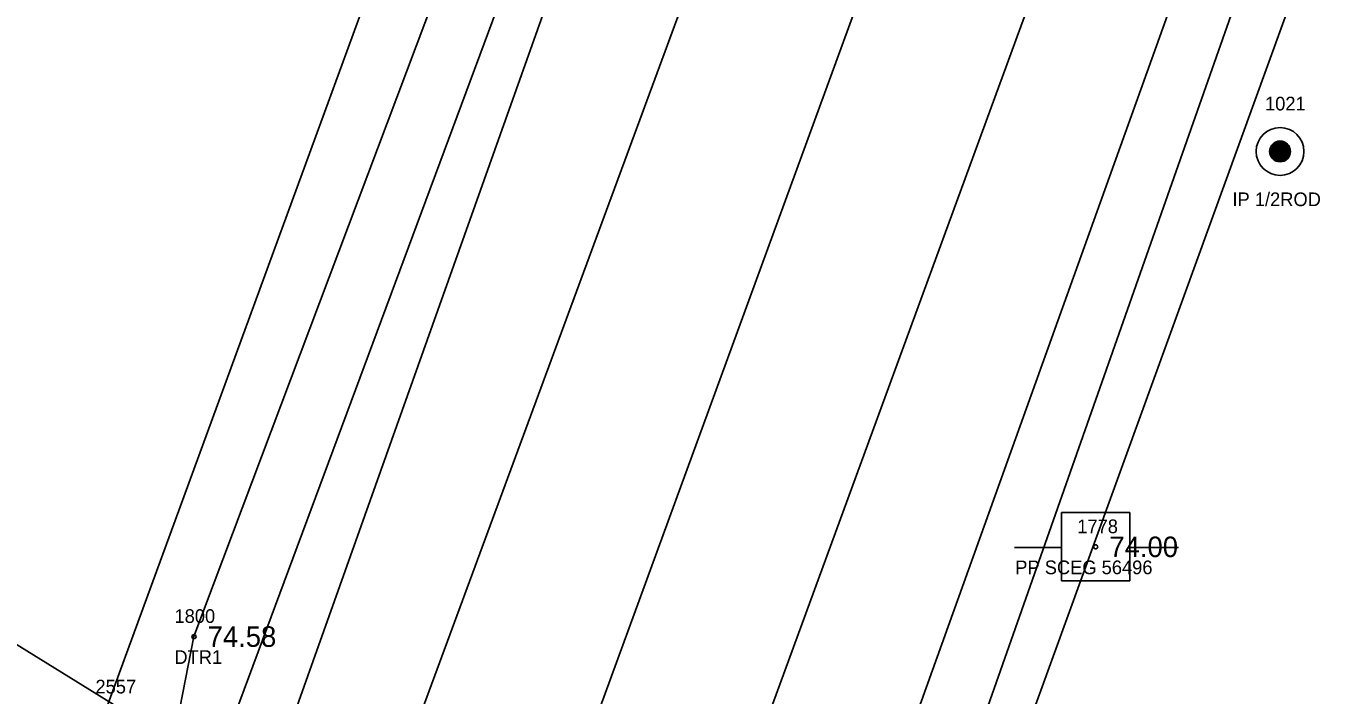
# Model space of a CAD drawing. Extents: x 2139392 to 2143384, y 505395 to 510520.
# Drawn here: x 2140931.1 to 2141025.8, y 509096.6 to 509145.6 of the extents above; entities that cross this region are included whole.
import ezdxf

# ---------------------------------------------------------------- set-up
doc = ezdxf.new("R2010")
doc.units = 0
for name, color, linetype in [('RD_EV_EX_Wetlands', 7, 'Continuous'), ('RD_EX_DV_Prop_txCode', 7, 'Continuous'), ('RD_EX_DV_PropPin', 7, 'Continuous'), ('RD_EX_H2O', 7, 'Continuous'), ('RD_EX_H2O_txCode', 7, 'Continuous'), ('RD_EX_Road', 7, 'Continuous'), ('RD_EX_TX_H2O_ELEV', 7, 'Continuous'), ('RD_EX_UT', 7, 'Continuous'), ('RD_EX_UT_txCode', 7, 'Continuous'), ('RD_EX_VEG', 7, 'Continuous'), ('RD_HC_Cl', 7, 'Continuous'), ('RD_HC_Survey_ELEV', 7, 'Continuous'), ('RD_SMD_Locator', 7, 'Continuous')]:
    doc.layers.add(name, color=color, linetype=linetype)

msp = doc.modelspace()

# ---------------------------------------------------------------- linework, layer by layer
at = {"layer": 'RD_EV_EX_Wetlands'}
for p, q in [((2141031.306, 509324.164), (2140691.527, 508408.628)), ((2141075.304, 509306.136), (2140751.402, 508384.33))]:
    msp.add_line(p, q, dxfattribs=at)
at = {"layer": 'RD_EX_DV_PropPin'}
for p, q in [((2141022.027, 509136.196), (2141022.027, 509136.588)), ((2141022.062, 509136.094), (2141022.062, 509136.69)), ((2141022.097, 509136.022), (2141022.097, 509136.762)), ((2141022.132, 509135.965), (2141022.132, 509136.819)), ((2141022.167, 509135.918), (2141022.167, 509136.866)), ((2141022.202, 509135.877), (2141022.202, 509136.907)), ((2141022.237, 509135.841), (2141022.237, 509136.943)), ((2141022.272, 509135.81), (2141022.272, 509136.974)), ((2141022.307, 509135.782), (2141022.307, 509137.002)), ((2141022.342, 509135.757), (2141022.342, 509137.027)), ((2141022.377, 509135.736), (2141022.377, 509137.048)), ((2141022.412, 509135.716), (2141022.412, 509137.068)), ((2141022.447, 509135.699), (2141022.447, 509137.085)), ((2141022.482, 509135.684), (2141022.482, 509137.1)), ((2141022.517, 509135.672), (2141022.517, 509137.112)), ((2141022.552, 509135.661), (2141022.552, 509137.123)), ((2141022.587, 509135.651), (2141022.587, 509137.133)), ((2141022.622, 509135.644), (2141022.622, 509137.14)), ((2141022.657, 509135.638), (2141022.657, 509137.146)), ((2141022.692, 509135.634), (2141022.692, 509137.15)), ((2141022.727, 509135.632), (2141022.727, 509137.152)), ((2141022.762, 509135.631), (2141022.762, 509137.153)), ((2141022.797, 509135.632), (2141022.797, 509137.152)), ((2141022.833, 509135.634), (2141022.833, 509137.15)), ((2141022.868, 509135.638), (2141022.868, 509137.146)), ((2141022.903, 509135.644), (2141022.903, 509137.14)), ((2141022.938, 509135.651), (2141022.938, 509137.133)), ((2141022.973, 509135.661), (2141022.973, 509137.123)), ((2141023.008, 509135.672), (2141023.008, 509137.112)), ((2141023.043, 509135.684), (2141023.043, 509137.1)), ((2141023.078, 509135.699), (2141023.078, 509137.085)), ((2141023.113, 509135.716), (2141023.113, 509137.068)), ((2141023.148, 509135.736), (2141023.148, 509137.048)), ((2141023.183, 509135.757), (2141023.183, 509137.027)), ((2141023.218, 509135.782), (2141023.218, 509137.002)), ((2141023.253, 509135.81), (2141023.253, 509136.974)), ((2141023.288, 509135.841), (2141023.288, 509136.943)), ((2141023.323, 509135.877), (2141023.323, 509136.907)), ((2141023.358, 509135.918), (2141023.358, 509136.866)), ((2141023.393, 509135.965), (2141023.393, 509136.819)), ((2141023.428, 509136.022), (2141023.428, 509136.762)), ((2141023.463, 509136.094), (2141023.463, 509136.69)), ((2141023.498, 509136.196), (2141023.498, 509136.588))]:
    msp.add_line(p, q, dxfattribs=at)
for radius in [1.75, 0.761]:
    msp.add_circle((2141022.762, 509136.392), radius, dxfattribs=at)
at = {"layer": 'RD_EX_H2O'}
for points in [[(2141109.57, 509415.73), (2141114.373, 509420.617), (2141120.575, 509418.468), (2141123.731, 509414.719), (2141106.652, 509363.278), (2141087.87, 509318.683), (2141079.163, 509303.209), (2141069.29, 509273.889), (2141065.763, 509268.541), (2141032.314, 509171.571), (2140998.874, 509079.361), (2140999.098, 509067.338)], [(2141109.57, 509415.73), (2141094.185, 509368.738), (2141059.481, 509270.332), (2141024.495, 509174.17), (2140991.165, 509081.187), (2140987.702, 509072.107)], [(2141025.18, 509330.004), (2141009.078, 509287.11), (2140976.481, 509188.975), (2140943.34, 509100.907), (2140941.691, 509092.552)], [(2141025.18, 509330.004), (2141033.423, 509326.189), (2141034.031, 509320.599), (2141020.737, 509281.868), (2140983.567, 509187.835), (2140949.439, 509091.794), (2140950.117, 509084.291)], [(2140941.691, 509092.552), (2140937.766, 509095.748), (2140924.442, 509103.995), (2140920.422, 509116.79)]]:
    msp.add_lwpolyline(points, dxfattribs=at)
at = {"layer": 'RD_EX_Road'}
for points in [[(2141086.274, 509371.268), (2141050.416, 509272.831), (2141015.083, 509176.386), (2140981.032, 509083.349), (2140979.152, 509077.9), (2140973.702, 509063.543), (2140966.529, 509043.246), (2140933.444, 508952.985), (2140896.921, 508852.594), (2140862.176, 508757.775), (2140824.897, 508656.318), (2140789.814, 508560.303), (2140766.773, 508496.85), (2140751.904, 508457.035), (2140731.87, 508401.538), (2140727.357, 508390.267)], [(2141052.52, 509348.478), (2141043.476, 509323.884), (2141027.845, 509280.545), (2140992.949, 509184.866), (2140958.528, 509091.45), (2140950.798, 509069.471), (2140944.28, 509052.058), (2140911.452, 508962.099), (2140874.646, 508861.605), (2140839.422, 508765.216), (2140802.376, 508664.564), (2140767.791, 508569.67), (2140744.17, 508504.83), (2140729.493, 508465.071), (2140707.156, 508404.621), (2140705.357, 508398.025)]]:
    msp.add_lwpolyline(points, dxfattribs=at)
at = {"layer": 'RD_EX_UT'}
for p, q in [((2141011.771, 509109.98), (2141006.771, 509109.98)), ((2141006.771, 509109.98), (2141006.771, 509104.98)), ((2141011.771, 509104.98), (2141011.771, 509109.98)), ((2141003.34, 509107.417), (2141006.809, 509107.417)), ((2141011.699, 509107.417), (2141015.34, 509107.417)), ((2141006.771, 509104.98), (2141011.771, 509104.98))]:
    msp.add_line(p, q, dxfattribs=at)
at = {"layer": 'RD_EX_VEG'}
msp.add_lwpolyline([(2140900.084, 509397.36), (2141021.293, 509326.195), (2140852.613, 508865.264), (2140689.341, 508413.458), (2140624.535, 508226.483), (2140606.41, 508171.784), (2140591.23, 508116.672), (2140558.821, 507962.773), (2140538.778, 507709.071), (2140410.608, 507724.882)], dxfattribs=at)
at = {"layer": 'RD_HC_Cl'}
msp.add_line((2141333.53, 510081.693), (2140670.514, 508268.365), dxfattribs=at)
at = {"layer": 'RD_SMD_Locator'}
for centre in [(2141022.763, 509136.392), (2141009.28, 509107.471), (2140943.34, 509100.907)]:
    msp.add_circle(centre, 0.15, dxfattribs=at)

# ---------------------------------------------------------------- texts
at = {"layer": 'RD_EX_DV_Prop_txCode'}
for s, p in [('1021', (2141021.66, 509139.392)), ('IP 1/2ROD', (2141019.282, 509132.392))]:
    msp.add_text(s, height=1, dxfattribs=at).set_placement(p)
at = {"layer": 'RD_EX_H2O_txCode'}
for s, p in [('1800', (2140941.915, 509101.907)), ('DTR1', (2140941.907, 509098.907)), ('2557', (2140936.136, 509096.748))]:
    msp.add_text(s, height=1, dxfattribs=at).set_placement(p)
at = {"layer": 'RD_EX_TX_H2O_ELEV'}
msp.add_text('74.58', height=1.5, dxfattribs=at).set_placement((2140944.34, 509100.157))
at = {"layer": 'RD_EX_UT_txCode'}
for s, p in [('1778', (2141007.933, 509108.471)), ('PP SCEG 56496', (2141003.398, 509105.471))]:
    msp.add_text(s, height=1, dxfattribs=at).set_placement(p)
at = {"layer": 'RD_HC_Survey_ELEV'}
msp.add_text('74.00', height=1.5, dxfattribs=at).set_placement((2141010.28, 509106.721))

doc.saveas('drawing.dxf')
